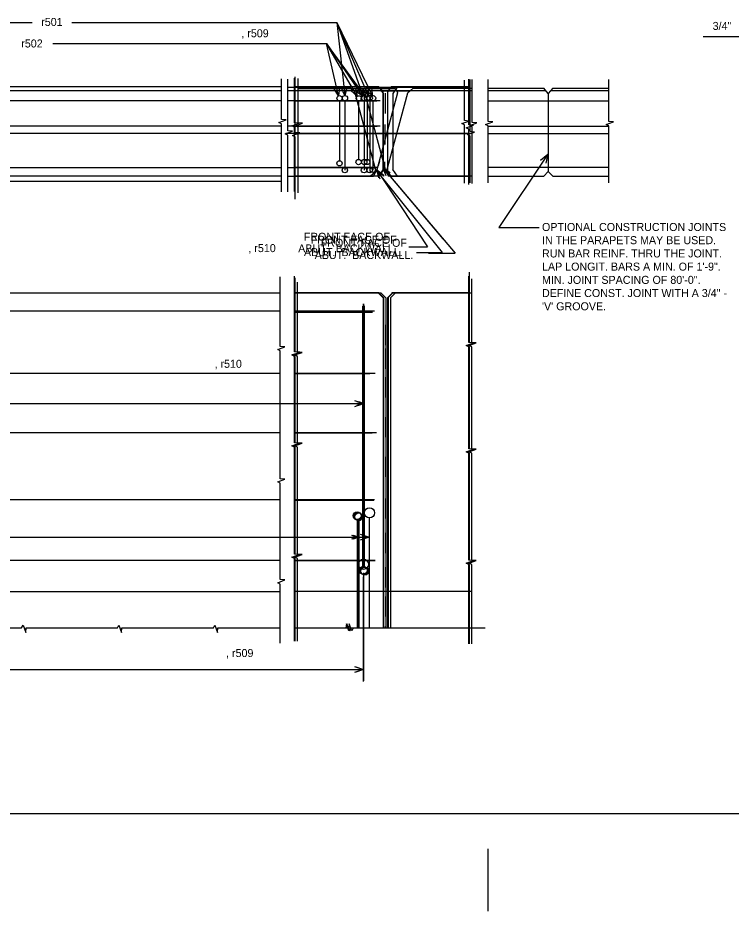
# Model space of a CAD drawing. Extents: x -81 to -44.8, y 85.9 to 111.1.
# Drawn here: x -69.45 to -58.31, y 86.67 to 100.62 of the extents above; entities that cross this region are included whole.
import ezdxf

# ---------------------------------------------------------------- set-up
doc = ezdxf.new("R2010")
doc.units = 0
for name, color, linetype in [('Default', 7, 'Continuous'), ('Level 1', 7, 'Continuous'), ('Level 12', 7, 'Continuous'), ('Level 13', 7, 'Continuous'), ('Level 14', 7, 'Continuous'), ('Level 15', 7, 'Continuous'), ('Level 2', 7, 'Continuous'), ('Level 37', 7, 'Continuous'), ('Level 5', 7, 'Continuous'), ('Level 9', 7, 'Continuous')]:
    doc.layers.add(name, color=color, linetype=linetype)

msp = doc.modelspace()

# ---------------------------------------------------------------- linework, layer by layer
at = {"layer": 'Default'}
for p, q in [((-61.199, 99.483), (-62.101, 99.483)), ((-60.216, 99.483), (-61.128, 99.483)), ((-62.101, 99.328), (-60.216, 99.328)), ((-62.101, 98.928), (-60.216, 98.928)), ((-62.101, 98.289), (-60.216, 98.289))]:
    msp.add_line(p, q, dxfattribs=at)
at = {"layer": 'Level 1'}
for p, q in [((-58.743, 100.332), (-58.16, 100.332)), ((-77.797, 88.192), (-46.422, 88.192))]:
    msp.add_line(p, q, dxfattribs=at)
at = {"layer": 'Level 12'}
for p, q in [((-63.972, 99.406), (-64.469, 100.55)), ((-64.63, 100.22), (-64.067, 99.4)), ((-63.811, 99.545), (-65.129, 99.545)), ((-63.812, 99.547), (-63.749, 99.468)), ((-63.62, 99.547), (-63.675, 99.468)), ((-62.406, 99.545), (-63.621, 99.545)), ((-63.782, 99.483), (-65.129, 99.483)), ((-63.782, 99.483), (-63.646, 99.483)), ((-63.749, 99.468), (-63.749, 98.228)), ((-63.713, 99.445), (-63.713, 99.128)), ((-63.675, 99.468), (-63.675, 98.228)), ((-62.406, 99.483), (-63.646, 99.483)), ((-65.129, 99.328), (-63.844, 99.328)), ((-64.039, 99.328), (-64.039, 98.368)), ((-63.955, 99.328), (-63.955, 98.243)), ((-63.719, 98.959), (-63.719, 98.642)), ((-65.156, 98.928), (-63.838, 98.928)), ((-65.129, 98.816), (-63.749, 98.816)), ((-63.675, 98.816), (-62.406, 98.816)), ((-65.129, 98.289), (-63.831, 98.289)), ((-63.724, 98.375), (-63.724, 98.228)), ((-63.675, 98.328), (-63.675, 98.25)), ((-63.812, 98.149), (-65.129, 98.149)), ((-63.812, 98.149), (-63.749, 98.228)), ((-63.62, 98.149), (-63.675, 98.228)), ((-63.62, 98.149), (-62.406, 98.149)), ((-65.129, 96.328), (-63.825, 96.328)), ((-63.747, 96.251), (-63.825, 96.328)), ((-63.675, 96.251), (-63.598, 96.327)), ((-63.613, 96.328), (-62.406, 96.328)), ((-64.05, 96.154), (-64.05, 92.144)), ((-63.747, 96.251), (-63.747, 91.088)), ((-63.702, 96.224), (-63.702, 95.907)), ((-63.675, 96.251), (-63.675, 91.088)), ((-63.955, 96.021), (-65.129, 96.021)), ((-63.71, 95.827), (-63.71, 95.51)), ((-63.71, 95.456), (-63.71, 95.14)), ((-65.129, 95.065), (-63.954, 95.065)), ((-63.71, 95.007), (-63.71, 94.69)), ((-65.352, 94.597), (-64.05, 94.597)), ((-63.71, 94.387), (-63.71, 94.07)), ((-65.129, 94.138), (-63.918, 94.138)), ((-63.71, 93.766), (-63.71, 93.45)), ((-63.937, 93.082), (-65.129, 93.082)), ((-63.707, 93.115), (-63.707, 92.799)), ((-63.965, 92.816), (-63.965, 91.093)), ((-63.707, 92.579), (-63.707, 92.262)), ((-65.352, 92.51), (-63.965, 92.51)), ((-65.129, 92.144), (-63.87, 92.144)), ((-63.708, 92.042), (-63.708, 91.726)), ((-64.05, 91.954), (-64.05, 90.263)), ((-62.406, 91.661), (-65.129, 91.661)), ((-63.708, 91.585), (-63.708, 91.268)), ((-63.711, 91.116), (-63.711, 91.088))]:
    msp.add_line(p, q, dxfattribs=at)
for points in [[(-65.129, 97.908), (-65.129, 98.914), (-65.17, 98.936), (-65.058, 98.977), (-65.129, 98.983), (-65.129, 99.681)], [(-62.406, 98.017), (-62.406, 98.882), (-62.447, 98.904), (-62.335, 98.945), (-62.406, 98.951), (-62.406, 99.663)], [(-64.106, 99.543), (-64.067, 99.4), (-64.187, 99.488)], [(-63.984, 99.555), (-63.972, 99.406), (-64.073, 99.516)], [(-65.129, 94.622), (-65.129, 95.334), (-65.17, 95.356), (-65.058, 95.397), (-65.129, 95.403), (-65.129, 96.588)], [(-62.406, 94.77), (-62.406, 95.482), (-62.447, 95.504), (-62.335, 95.545), (-62.406, 95.551), (-62.406, 96.552)], [(-62.406, 93.109), (-62.406, 93.821), (-62.447, 93.843), (-62.335, 93.884), (-62.406, 93.89), (-62.406, 94.77)], [(-65.129, 93.202), (-65.129, 93.914), (-65.17, 93.935), (-65.058, 93.977), (-65.129, 93.983), (-65.129, 94.622)], [(-64.191, 94.646), (-64.05, 94.597), (-64.191, 94.548)], [(-65.129, 90.887), (-65.129, 92.177), (-65.17, 92.199), (-65.058, 92.24), (-65.129, 92.246), (-65.129, 93.219)], [(-62.406, 90.842), (-62.406, 92.085), (-62.447, 92.106), (-62.335, 92.148), (-62.406, 92.153), (-62.406, 93.126)], [(-64.106, 92.559), (-63.965, 92.51), (-64.106, 92.462)], [(-62.195, 91.088), (-64.257, 91.088), (-64.279, 91.046), (-64.32, 91.158), (-64.326, 91.088), (-65.129, 91.088)], [(-64.191, 90.491), (-64.05, 90.443), (-64.191, 90.394)]]:
    msp.add_lwpolyline(points, dxfattribs=at)
for centre, radius in [((-64.039, 99.367), 0.0417), ((-63.955, 99.369), 0.0417), ((-64.039, 98.37), 0.0417), ((-63.955, 98.243), 0.0417), ((-63.958, 92.89), 0.0788), ((-64.053, 92.086), 0.0788)]:
    msp.add_circle(centre, radius, dxfattribs=at)
at = {"layer": 'Level 13'}
for p, q in [((-64.469, 100.55), (-63.909, 99.397)), ((-64.015, 99.385), (-64.63, 100.22)), ((-65.101, 99.545), (-63.813, 99.545)), ((-63.813, 99.545), (-63.742, 99.443)), ((-63.521, 99.545), (-63.593, 99.442)), ((-63.521, 99.545), (-62.392, 99.545)), ((-63.769, 99.483), (-65.12, 99.483)), ((-63.769, 99.483), (-63.565, 99.483)), ((-63.742, 99.443), (-63.742, 98.251)), ((-63.593, 99.442), (-63.593, 98.253)), ((-62.387, 99.483), (-63.565, 99.483)), ((-63.829, 99.328), (-65.12, 99.328)), ((-63.993, 99.328), (-63.993, 98.396)), ((-63.908, 99.328), (-63.908, 98.249)), ((-63.829, 98.928), (-65.12, 98.928)), ((-63.742, 98.816), (-65.074, 98.816)), ((-62.379, 98.816), (-63.593, 98.816)), ((-65.12, 98.284), (-63.829, 98.284)), ((-63.813, 98.149), (-63.742, 98.251)), ((-63.742, 98.273), (-62.811, 97.171)), ((-63.742, 98.273), (-62.621, 96.946)), ((-63.521, 98.149), (-63.593, 98.253)), ((-63.813, 98.149), (-65.12, 98.149)), ((-63.521, 98.149), (-62.387, 98.149)), ((-63.035, 96.946), (-62.621, 96.946)), ((-65.129, 96.327), (-63.825, 96.327)), ((-63.747, 96.249), (-63.825, 96.327)), ((-63.675, 96.249), (-63.598, 96.326)), ((-63.613, 96.327), (-62.406, 96.327)), ((-64.058, 96.155), (-64.058, 92.042)), ((-63.747, 96.249), (-63.747, 91.088)), ((-63.675, 96.249), (-63.675, 91.088)), ((-63.878, 96.039), (-65.129, 96.039)), ((-63.878, 95.065), (-65.129, 95.065)), ((-65.129, 94.597), (-64.058, 94.597)), ((-63.878, 94.138), (-65.129, 94.138)), ((-63.993, 93.095), (-65.129, 93.095)), ((-64.142, 92.776), (-64.142, 91.09)), ((-65.129, 92.51), (-64.142, 92.51)), ((-63.878, 92.144), (-65.129, 92.144)), ((-64.05, 91.868), (-64.05, 90.275)), ((-63.747, 91.661), (-65.129, 91.661)), ((-62.406, 91.661), (-63.675, 91.661))]:
    msp.add_line(p, q, dxfattribs=at)
for points in [[(-65.12, 97.789), (-65.12, 98.762), (-65.161, 98.784), (-65.049, 98.825), (-65.12, 98.831), (-65.12, 99.7)], [(-62.387, 98.047), (-62.387, 98.776), (-62.428, 98.798), (-62.316, 98.839), (-62.387, 98.845), (-62.387, 99.658)], [(-64.053, 99.506), (-64.015, 99.385), (-64.119, 99.457)], [(-63.925, 99.523), (-63.909, 99.397), (-63.999, 99.487)], [(-63.696, 98.155), (-63.742, 98.273), (-63.633, 98.208)], [(-62.406, 94.77), (-62.406, 95.482), (-62.447, 95.504), (-62.335, 95.545), (-62.406, 95.551), (-62.406, 96.587)], [(-65.129, 94.622), (-65.129, 95.334), (-65.17, 95.356), (-65.058, 95.397), (-65.129, 95.403), (-65.129, 96.545)], [(-62.406, 93.109), (-62.406, 93.821), (-62.447, 93.843), (-62.335, 93.884), (-62.406, 93.89), (-62.406, 94.77)], [(-65.129, 93.202), (-65.129, 93.914), (-65.17, 93.935), (-65.058, 93.977), (-65.129, 93.983), (-65.129, 94.622)], [(-64.146, 94.627), (-64.058, 94.597), (-64.146, 94.566)], [(-65.129, 90.887), (-65.129, 92.177), (-65.17, 92.199), (-65.058, 92.24), (-65.129, 92.246), (-65.129, 93.219)], [(-62.406, 90.842), (-62.406, 92.085), (-62.447, 92.106), (-62.335, 92.148), (-62.406, 92.153), (-62.406, 93.126)], [(-64.23, 92.541), (-64.142, 92.51), (-64.23, 92.48)], [(-62.195, 91.088), (-64.257, 91.088), (-64.279, 91.046), (-64.32, 91.158), (-64.326, 91.088), (-65.129, 91.088)], [(-64.17, 90.484), (-64.05, 90.443), (-64.17, 90.401)]]:
    msp.add_lwpolyline(points, dxfattribs=at)
for centre, radius in [((-63.996, 99.365), 0.0417), ((-63.902, 99.366), 0.0417), ((-63.995, 98.371), 0.0417), ((-63.908, 98.249), 0.0417), ((-64.142, 92.835), 0.061), ((-64.048, 91.988), 0.061)]:
    msp.add_circle(centre, radius, dxfattribs=at)
at = {"layer": 'Level 14'}
for p, q in [((-64.469, 100.55), (-64.342, 99.408)), ((-64.44, 99.404), (-64.63, 100.22)), ((-65.235, 99.542), (-64.277, 99.542)), ((-64.277, 99.542), (-64.191, 99.473)), ((-63.994, 99.542), (-64.036, 99.463)), ((-63.994, 99.542), (-62.474, 99.542)), ((-64.194, 99.483), (-65.235, 99.483)), ((-64.194, 99.483), (-64.025, 99.483)), ((-64.191, 99.473), (-63.857, 98.225)), ((-64.036, 99.463), (-63.703, 98.219)), ((-62.474, 99.483), (-64.025, 99.483)), ((-64.27, 99.328), (-65.235, 99.328)), ((-64.428, 99.328), (-64.428, 98.38)), ((-64.343, 99.328), (-64.343, 98.243)), ((-64.015, 98.816), (-65.267, 98.816)), ((-64.27, 98.928), (-65.235, 98.928)), ((-62.474, 98.816), (-63.863, 98.816)), ((-63.746, 98.382), (-63.726, 98.306)), ((-65.235, 98.284), (-63.99, 98.284)), ((-65.235, 98.149), (-63.897, 98.149)), ((-63.857, 98.225), (-63.897, 98.149)), ((-63.838, 98.22), (-62.822, 96.959)), ((-63.703, 98.219), (-63.616, 98.149)), ((-63.616, 98.149), (-62.474, 98.149)), ((-63.223, 96.959), (-62.822, 96.959)), ((-65.083, 96.326), (-63.779, 96.326)), ((-63.701, 96.248), (-63.779, 96.326)), ((-63.629, 96.248), (-63.552, 96.325)), ((-63.567, 96.326), (-62.36, 96.326)), ((-63.701, 96.248), (-63.701, 91.088)), ((-63.629, 96.248), (-63.629, 91.088)), ((-63.909, 96.018), (-65.083, 96.018)), ((-64.066, 96.116), (-64.066, 92.045)), ((-63.871, 95.065), (-65.083, 95.065)), ((-65.083, 94.597), (-64.066, 94.597)), ((-63.847, 94.138), (-65.083, 94.138)), ((-63.891, 93.082), (-65.083, 93.082)), ((-64.151, 92.785), (-64.151, 91.093)), ((-65.083, 92.51), (-64.151, 92.51)), ((-63.871, 92.144), (-65.083, 92.144)), ((-64.05, 90.298), (-64.05, 91.883)), ((-63.701, 91.661), (-65.083, 91.661)), ((-62.36, 91.661), (-63.629, 91.661))]:
    msp.add_line(p, q, dxfattribs=at)
for points in [[(-65.235, 97.903), (-65.235, 98.791), (-65.276, 98.813), (-65.164, 98.854), (-65.235, 98.86), (-65.235, 99.667)], [(-62.474, 98.038), (-62.474, 98.949), (-62.515, 98.97), (-62.403, 99.011), (-62.474, 99.017), (-62.474, 99.649)], [(-64.427, 99.53), (-64.44, 99.404), (-64.508, 99.512)], [(-64.314, 99.532), (-64.342, 99.408), (-64.396, 99.523)], [(-63.792, 98.102), (-63.838, 98.22), (-63.729, 98.155)], [(-65.083, 94.622), (-65.083, 95.334), (-65.124, 95.356), (-65.012, 95.397), (-65.083, 95.403), (-65.083, 96.496)], [(-62.36, 94.77), (-62.36, 95.482), (-62.401, 95.504), (-62.289, 95.545), (-62.36, 95.551), (-62.36, 96.543)], [(-62.36, 93.109), (-62.36, 93.821), (-62.401, 93.843), (-62.289, 93.884), (-62.36, 93.89), (-62.36, 94.77)], [(-65.083, 93.202), (-65.083, 93.914), (-65.124, 93.935), (-65.012, 93.977), (-65.083, 93.983), (-65.083, 94.622)], [(-64.154, 94.627), (-64.066, 94.597), (-64.154, 94.566)], [(-65.083, 90.887), (-65.083, 92.177), (-65.124, 92.199), (-65.012, 92.24), (-65.083, 92.246), (-65.083, 93.219)], [(-62.36, 90.842), (-62.36, 92.085), (-62.401, 92.106), (-62.289, 92.148), (-62.36, 92.153), (-62.36, 93.126)], [(-64.239, 92.541), (-64.151, 92.51), (-64.239, 92.48)], [(-62.149, 91.088), (-64.211, 91.088), (-64.233, 91.046), (-64.274, 91.158), (-64.28, 91.088), (-65.083, 91.088)], [(-64.17, 90.484), (-64.05, 90.443), (-64.17, 90.401)]]:
    msp.add_lwpolyline(points, dxfattribs=at)
for centre, radius in [((-64.426, 99.367), 0.0417), ((-64.342, 99.368), 0.0417), ((-64.427, 98.351), 0.0417), ((-64.343, 98.243), 0.0417), ((-64.151, 92.845), 0.061), ((-64.057, 91.991), 0.061)]:
    msp.add_circle(centre, radius, dxfattribs=at)
at = {"layer": 'Level 15'}
for p, q in [((-64.469, 100.55), (-64.055, 99.395)), ((-64.15, 99.398), (-64.63, 100.22)), ((-65.074, 99.518), (-63.554, 99.518)), ((-63.554, 99.518), (-63.518, 99.452)), ((-63.273, 99.523), (-63.366, 99.448)), ((-63.273, 99.523), (-62.351, 99.523)), ((-63.535, 99.483), (-65.074, 99.483)), ((-63.518, 99.452), (-63.847, 98.225)), ((-63.366, 99.448), (-63.697, 98.213)), ((-63.535, 99.483), (-63.323, 99.483)), ((-62.351, 99.483), (-63.323, 99.483)), ((-63.791, 99.328), (-65.074, 99.328)), ((-64.128, 99.328), (-64.128, 98.411)), ((-64.044, 99.328), (-64.044, 98.243)), ((-63.791, 98.928), (-65.074, 98.928)), ((-63.689, 98.816), (-65.074, 98.816)), ((-62.351, 98.816), (-63.535, 98.816)), ((-63.804, 98.386), (-63.824, 98.31)), ((-65.074, 98.284), (-63.963, 98.284)), ((-63.841, 98.249), (-63.05, 97.043)), ((-63.94, 98.149), (-65.074, 98.149)), ((-63.847, 98.225), (-63.94, 98.149)), ((-63.697, 98.213), (-63.663, 98.149)), ((-62.351, 98.149), (-63.663, 98.149)), ((-63.344, 97.043), (-63.05, 97.043)), ((-65.119, 96.331), (-63.815, 96.331)), ((-63.737, 96.254), (-63.815, 96.331)), ((-63.665, 96.254), (-63.588, 96.33)), ((-63.603, 96.331), (-62.396, 96.331)), ((-63.737, 96.254), (-63.737, 91.088)), ((-63.665, 96.254), (-63.665, 91.088)), ((-63.881, 96.039), (-65.119, 96.039)), ((-64.041, 96.124), (-64.041, 92.034)), ((-63.881, 95.065), (-65.119, 95.065)), ((-65.119, 94.597), (-64.041, 94.597)), ((-63.881, 94.138), (-65.119, 94.138)), ((-63.881, 93.095), (-65.119, 93.095)), ((-64.126, 92.768), (-64.126, 91.082)), ((-65.119, 92.51), (-64.126, 92.51)), ((-63.881, 92.144), (-65.119, 92.144)), ((-64.05, 90.255), (-64.05, 91.892)), ((-62.396, 91.661), (-65.119, 91.661))]:
    msp.add_line(p, q, dxfattribs=at)
for points in [[(-65.074, 97.889), (-65.074, 98.916), (-65.115, 98.937), (-65.003, 98.979), (-65.074, 98.985), (-65.074, 99.674)], [(-62.351, 98.036), (-62.351, 98.92), (-62.392, 98.942), (-62.28, 98.983), (-62.351, 98.989), (-62.351, 99.658)], [(-64.175, 99.522), (-64.15, 99.398), (-64.246, 99.481)], [(-64.057, 99.521), (-64.055, 99.395), (-64.135, 99.493)], [(-63.81, 98.126), (-63.841, 98.249), (-63.74, 98.171)], [(-62.396, 94.77), (-62.396, 95.482), (-62.437, 95.504), (-62.325, 95.545), (-62.396, 95.551), (-62.396, 96.652)], [(-65.119, 94.622), (-65.119, 95.334), (-65.16, 95.356), (-65.048, 95.397), (-65.119, 95.403), (-65.119, 96.559)], [(-62.396, 93.109), (-62.396, 93.821), (-62.437, 93.843), (-62.325, 93.884), (-62.396, 93.89), (-62.396, 94.77)], [(-65.119, 93.202), (-65.119, 93.914), (-65.16, 93.935), (-65.048, 93.977), (-65.119, 93.983), (-65.119, 94.622)], [(-64.129, 94.627), (-64.041, 94.597), (-64.129, 94.566)], [(-65.119, 90.887), (-65.119, 92.177), (-65.16, 92.199), (-65.048, 92.24), (-65.119, 92.246), (-65.119, 93.219)], [(-62.396, 90.842), (-62.396, 92.085), (-62.437, 92.106), (-62.325, 92.148), (-62.396, 92.153), (-62.396, 93.126)], [(-64.214, 92.541), (-64.126, 92.51), (-64.214, 92.48)], [(-62.185, 91.088), (-64.247, 91.088), (-64.269, 91.046), (-64.31, 91.158), (-64.316, 91.088), (-65.119, 91.088)], [(-64.17, 90.484), (-64.05, 90.443), (-64.17, 90.401)]]:
    msp.add_lwpolyline(points, dxfattribs=at)
for centre, radius in [((-64.125, 99.365), 0.0417), ((-64.044, 99.364), 0.0417), ((-64.128, 98.37), 0.0417), ((-64.044, 98.243), 0.0417), ((-64.127, 92.828), 0.061), ((-64.031, 91.98), 0.061)]:
    msp.add_circle(centre, radius, dxfattribs=at)
at = {"layer": 'Level 2'}
for p, q in [((-62.101, 99.523), (-61.234, 99.523)), ((-61.163, 99.443), (-61.234, 99.523)), ((-61.092, 99.523), (-61.163, 99.443)), ((-61.092, 99.523), (-60.216, 99.523)), ((-61.163, 99.443), (-61.163, 98.221)), ((-62.101, 98.816), (-60.216, 98.816)), ((-62.101, 98.149), (-61.235, 98.149)), ((-61.163, 98.221), (-61.235, 98.149)), ((-61.163, 98.221), (-61.091, 98.149)), ((-61.091, 98.149), (-60.216, 98.149))]:
    msp.add_line(p, q, dxfattribs=at)
for points in [[(-62.101, 98.047), (-62.101, 98.937), (-62.143, 98.958), (-62.03, 99), (-62.101, 99.005), (-62.101, 99.659)], [(-60.216, 98.047), (-60.216, 98.937), (-60.257, 98.958), (-60.145, 99), (-60.216, 99.005), (-60.216, 99.658)], [(-61.17, 98.495), (-61.938, 97.349), (-61.305, 97.349)], [(-61.286, 98.401), (-61.17, 98.495), (-61.203, 98.35)]]:
    msp.add_lwpolyline(points, dxfattribs=at)
at = {"layer": 'Level 37'}
msp.add_line((-62.109, 87.64), (-62.109, 86.668), dxfattribs=at)
at = {"layer": 'Level 5'}
for p, q in [((-74.821, 100.55), (-69.231, 100.55)), ((-68.611, 100.55), (-64.469, 100.55)), ((-68.91, 100.22), (-64.63, 100.22)), ((-65.333, 99.545), (-75.839, 99.545)), ((-65.333, 99.483), (-75.839, 99.483)), ((-65.333, 99.328), (-75.762, 99.328)), ((-65.333, 98.816), (-75.839, 98.816)), ((-65.333, 98.928), (-75.762, 98.928)), ((-75.762, 98.284), (-65.333, 98.284)), ((-65.333, 98.149), (-75.839, 98.149)), ((-65.333, 98.066), (-75.839, 98.066)), ((-75.844, 96.328), (-65.352, 96.328)), ((-65.352, 96.039), (-75.749, 96.039)), ((-65.352, 95.065), (-75.749, 95.065)), ((-70.285, 94.597), (-65.352, 94.597)), ((-65.352, 94.138), (-75.749, 94.138)), ((-65.352, 93.095), (-75.749, 93.095)), ((-70.285, 92.51), (-65.352, 92.51)), ((-65.352, 92.144), (-75.749, 92.144)), ((-75.844, 91.661), (-65.352, 91.661)), ((-75.581, 90.443), (-64.05, 90.443))]:
    msp.add_line(p, q, dxfattribs=at)
for points in [[(-65.333, 97.903), (-65.333, 98.966), (-65.374, 98.988), (-65.262, 99.029), (-65.333, 99.035), (-65.333, 99.669)], [(-65.352, 94.709), (-65.352, 95.421), (-65.393, 95.443), (-65.281, 95.484), (-65.352, 95.49), (-65.352, 96.576)], [(-65.352, 92.819), (-65.352, 93.352), (-65.393, 93.373), (-65.281, 93.414), (-65.352, 93.42), (-65.352, 94.702)], [(-65.352, 90.852), (-65.352, 91.778), (-65.393, 91.799), (-65.281, 91.841), (-65.352, 91.846), (-65.352, 92.819)], [(-70.107, 91.093), (-69.395, 91.093), (-69.373, 91.134), (-69.332, 91.022), (-69.326, 91.093), (-68.359, 91.093)], [(-68.369, 91.093), (-67.896, 91.093), (-67.874, 91.134), (-67.833, 91.022), (-67.827, 91.093), (-67.108, 91.093)], [(-67.108, 91.093), (-66.396, 91.093), (-66.374, 91.134), (-66.333, 91.022), (-66.327, 91.093), (-65.352, 91.093)]]:
    msp.add_lwpolyline(points, dxfattribs=at)

# ---------------------------------------------------------------- texts
at = {"layer": 'Level 1'}
msp.add_text('3/4"', height=0.125, dxfattribs=at).set_placement((-58.595, 100.434))
at = {"layer": 'Level 13'}
for s, p in [('FRONT FACE OF', (-64.72, 97.046)), (' ABUT.  BACKWALL.', (-64.861, 96.855))]:
    msp.add_text(s, height=0.125, dxfattribs=at).set_placement(p)
at = {"layer": 'Level 14'}
for s, p in [('FRONT FACE OF', (-64.878, 97.093)), (' ABUT.  BACKWALL.', (-65.029, 96.9))]:
    msp.add_text(s, height=0.125, dxfattribs=at).set_placement(p)
at = {"layer": 'Level 15'}
for s, p in [('FRONT FACE OF ', (-64.985, 97.14)), (' ABUT.  BACKWALL.', (-65.119, 96.958))]:
    msp.add_text(s, height=0.125, dxfattribs=at).set_placement(p)
at = {"layer": 'Level 2'}
for s, p in [('OPTIONAL CONSTRUCTION JOINTS', (-61.262, 97.293)), ('IN THE PARAPETS MAY BE USED.', (-61.262, 97.087)), ('RUN BAR REINF. THRU THE JOINT.', (-61.262, 96.88)), ('LAP LONGIT. BARS A MIN. OF 1\'-9".', (-61.262, 96.674)), ('MIN. JOINT SPACING OF 80\'-0".', (-61.262, 96.467)), ('DEFINE CONST. JOINT WITH A 3/4" -', (-61.262, 96.261)), ("'V' GROOVE.", (-61.262, 96.054))]:
    msp.add_text(s, height=0.125, dxfattribs=at).set_placement(p)
at = {"layer": 'Level 5'}
for s, p in [('r501', (-69.089, 100.496)), ('r502', (-69.401, 100.16))]:
    msp.add_text(s, height=0.125, dxfattribs=at).set_placement(p)
at = {"layer": 'Level 9'}
for s, p in [(', r509', (-65.961, 100.319)), (', r510', (-65.851, 96.963)), (', r510', (-66.38, 95.156)), (', r509', (-66.2, 90.637))]:
    msp.add_text(s, height=0.125, dxfattribs=at).set_placement(p)

doc.saveas('drawing.dxf')
